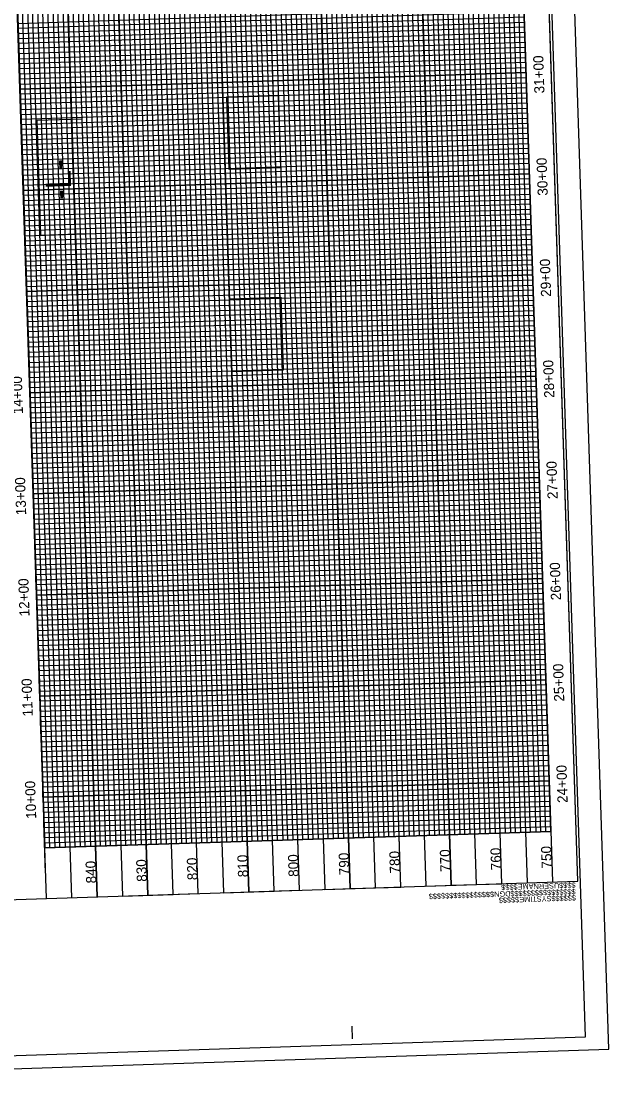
# Model space of a CAD drawing. Extents: x 1627314 to 1628469, y 762309 to 764212.
# Drawn here: x 1627889 to 1628469, y 762309 to 763361 of the extents above; entities that cross this region are included whole.
import ezdxf

# ---------------------------------------------------------------- set-up
doc = ezdxf.new("R2010")
doc.units = 0
for name, color, linetype in [('Exist Vertical Profile Horizontal Axis Label Major', 7, 'Continuous'), ('Exist Vertical Profile Vertical Axis Label', 7, 'Continuous'), ('Prop DSN Text', 7, 'Continuous'), ('Prop Grid Mask', 7, 'Continuous'), ('Sheet DOT Grid CELL', 7, 'Continuous'), ('Sheet Layout Profile Border Port 2', 7, 'Continuous'), ('Sheet Plot Border Inside CELL', 7, 'Continuous'), ('Sheet Plot Border Outside CELL', 7, 'Continuous'), ('Sheet Profile CELL', 7, 'Continuous'), ('Sheet Profile Grid Major CELL', 7, 'Continuous'), ('Sheet Profile Grid Middle CELL', 7, 'Continuous'), ('Sheet Profile Grid Minor CELL', 7, 'Continuous')]:
    doc.layers.add(name, color=color, linetype=linetype)

msp = doc.modelspace()

# ---------------------------------------------------------------- linework, layer by layer
at = {"layer": 'Prop Grid Mask'}
for points in [[(1628094.6, 763214.4), (1628092.3, 763286.3), (1628142.9, 763288), (1628145.2, 763216)], [(1627952.9, 763151.2), (1627949.2, 763264.2), (1627904.5, 763262.7), (1627908.2, 763149.7)], [(1628097.1, 763014.6), (1628094.8, 763086.6), (1628145.4, 763088.2), (1628147.8, 763016.3)]]:
    msp.add_lwpolyline(points, close=True, dxfattribs=at)
at = {"layer": 'Sheet DOT Grid CELL'}
for p, q in [((1628213.9, 762504), (1628164.8, 764003.1)), ((1628263.9, 762505.6), (1628214.8, 764004.7)), ((1628313.8, 762507.3), (1628264.8, 764006.4)), ((1628363.8, 762508.9), (1628314.8, 764008)), ((1627914, 762494.2), (1627865, 763993.3)), ((1627964, 762495.8), (1627915, 763994.9)), ((1628014, 762497.5), (1627965, 763996.6)), ((1628064, 762499.1), (1628014.9, 763998.2)), ((1628113.9, 762500.7), (1628064.9, 763999.8)), ((1628163.9, 762502.4), (1628114.9, 764001.5)), ((1627886.3, 763343.8), (1628386, 763360.1)), ((1627887.9, 763293.8), (1628387.6, 763310.1)), ((1627889.5, 763243.8), (1628389.3, 763260.2)), ((1627891.2, 763193.8), (1628390.9, 763210.2)), ((1627892.8, 763143.9), (1628392.5, 763160.2)), ((1627894.4, 763093.9), (1628394.2, 763110.2)), ((1627896.1, 763043.9), (1628395.8, 763060.3)), ((1627897.7, 762993.9), (1628397.4, 763010.3)), ((1627899.3, 762944), (1628399.1, 762960.3)), ((1627901, 762894), (1628400.7, 762910.3)), ((1627902.6, 762844), (1628402.3, 762860.4)), ((1627904.2, 762794), (1628404, 762810.4)), ((1627905.9, 762744.1), (1628405.6, 762760.4)), ((1627907.5, 762694.1), (1628407.2, 762710.4)), ((1627909.1, 762644.1), (1628408.9, 762660.5)), ((1627910.8, 762594.2), (1628410.5, 762610.5)), ((1627912.4, 762544.2), (1628412.1, 762560.5))]:
    msp.add_line(p, q, dxfattribs=at)
at = {"layer": 'Sheet Layout Profile Border Port 2'}
for points in [[(1627912.4, 762544.2), (1627866.6, 763943.4), (1628366.4, 763959.8), (1628412.1, 762560.5)], [(1627912.4, 762544.2), (1628412.1, 762560.5), (1628366.4, 763959.8), (1627866.6, 763943.4)]]:
    msp.add_lwpolyline(points, close=True, dxfattribs=at)
at = {"layer": 'Sheet Plot Border Inside CELL'}
msp.add_lwpolyline([(1628446.3, 762357.5), (1628391.9, 764023.1), (1627337.3, 763988.6), (1627391.8, 762323)], close=True, dxfattribs=at)
at = {"layer": 'Sheet Plot Border Outside CELL'}
msp.add_lwpolyline([(1628469.2, 762345.3), (1628413.6, 764044.4), (1627314.2, 764008.4), (1627369.8, 762309.3)], close=True, dxfattribs=at)
at = {"layer": 'Sheet Profile CELL'}
for p, q in [((1628364.7, 764009.7), (1628413.8, 762510.6)), ((1628438.8, 762511.4), (1628389.7, 764010.6)), ((1627914, 762494.2), (1627865, 763993.4)), ((1628438.8, 762511.4), (1628438.8, 762511.4)), ((1628438.8, 762511.4), (1628438.8, 762511.4)), ((1628438.8, 762511.4), (1628438.8, 762511.4)), ((1628438.8, 762511.4), (1628438.8, 762511.4)), ((1628438.8, 762511.4), (1628438.8, 762511.4)), ((1628438.8, 762511.4), (1628438.8, 762511.4)), ((1628438.8, 762511.4), (1628438.8, 762511.4)), ((1628216.2, 762355.5), (1628215.8, 762368))]:
    msp.add_line(p, q, dxfattribs=at)
msp.add_lwpolyline([(1627340.3, 763976.2), (1627389.3, 762477), (1628438.8, 762511.4), (1628389.7, 764010.6)], close=True, dxfattribs=at)
msp.add_lwpolyline([(1628437.5, 762548.8), (1628437.5, 762548.8)], dxfattribs=at)
at = {"layer": 'Sheet Profile Grid Major CELL'}
for p, q in [((1627891.2, 763193.8), (1627889.5, 763243.8)), ((1627894.4, 763093.9), (1627892.8, 763143.9)), ((1627897.7, 762993.9), (1627896.1, 763043.9)), ((1628413.8, 762510.6), (1628413.8, 762510.6))]:
    msp.add_line(p, q, dxfattribs=at)
for points in [[(1628164.8, 764003.2), (1628213.9, 762504), (1628263.9, 762505.6), (1628214.8, 764004.8)], [(1628264.8, 764006.5), (1628313.8, 762507.3), (1628313.8, 762507.3), (1628363.8, 762508.9), (1628314.8, 764008.1)], [(1628364.7, 764009.7), (1628413.8, 762510.6)], [(1627915, 763995), (1627964, 762495.8)], [(1627964.9, 763996.7), (1628014, 762497.5), (1628064, 762499.1), (1628014.9, 763998.3)], [(1628064.9, 763999.9), (1628113.9, 762500.7), (1628163.9, 762502.4), (1628114.9, 764001.6)], [(1627886.3, 763343.8), (1628386, 763360.1), (1628384.4, 763410.1)], [(1627912.4, 762544.2), (1628412.1, 762560.5), (1628410.5, 762610.5), (1627910.8, 762594.2), (1627909.1, 762644.1), (1628408.9, 762660.5), (1628407.2, 762710.4), (1627907.5, 762694.1), (1627905.9, 762744.1), (1628405.6, 762760.4), (1628404, 762810.4), (1627904.2, 762794), (1627902.6, 762844), (1628402.3, 762860.4), (1628400.7, 762910.3), (1627901, 762894), (1627899.3, 762944), (1628399.1, 762960.3), (1628397.4, 763010.3), (1627897.7, 762993.9), (1627896.1, 763043.9), (1628395.8, 763060.3), (1628394.2, 763110.2), (1627894.4, 763093.9), (1627892.8, 763143.9), (1628392.5, 763160.2), (1628390.9, 763210.2), (1627891.2, 763193.8), (1627889.5, 763243.8), (1628389.3, 763260.2), (1628387.6, 763310.1), (1627887.9, 763293.8)]]:
    msp.add_lwpolyline(points, dxfattribs=at)
at = {"layer": 'Sheet Profile Grid Middle CELL'}
for points in [[(1628139.9, 764002.4), (1628188.9, 762503.2), (1628238.9, 762504.8), (1628189.8, 764004)], [(1628239.8, 764005.7), (1628288.8, 762506.5), (1628338.8, 762508.1), (1628289.8, 764007.3)], [(1628339.7, 764008.9), (1628388.8, 762509.7)], [(1627939, 762495), (1627890, 763994.2)], [(1627940, 763995.9), (1627989, 762496.7), (1628039, 762498.3), (1627989.9, 763997.5)], [(1628039.9, 763999.1), (1628088.9, 762499.9), (1628138.9, 762501.6), (1628089.9, 764000.8)], [(1627913.2, 762519.2), (1627911.6, 762569.2), (1628411.3, 762585.5), (1628409.7, 762635.5), (1627910, 762619.1), (1627908.3, 762669.1), (1628408.1, 762685.5), (1628406.4, 762735.4), (1627906.7, 762719.1), (1627905.1, 762769.1), (1628404.8, 762785.4), (1628403.1, 762835.4), (1627903.4, 762819), (1627901.8, 762869), (1628401.5, 762885.4), (1628399.9, 762935.3), (1627900.1, 762919), (1627898.5, 762969), (1628398.2, 762985.3), (1628396.6, 763035.3), (1627896.9, 763018.9), (1627895.2, 763068.9), (1628395, 763085.2), (1628393.3, 763135.2), (1628393.3, 763135.2), (1627893.6, 763118.9), (1627892, 763168.8), (1628391.7, 763185.2), (1628390.1, 763235.2), (1627890.3, 763218.8), (1627888.7, 763268.8), (1628388.4, 763285.1), (1628386.8, 763335.1), (1627887.1, 763318.8)]]:
    msp.add_lwpolyline(points, dxfattribs=at)
at = {"layer": 'Sheet Profile Grid Minor CELL'}
for p, q in [((1628061.5, 763949.8), (1628107.2, 762550.5)), ((1628117.3, 762550.9), (1628071.5, 763950.1)), ((1628076.5, 763950.3), (1628122.3, 762551)), ((1628127.3, 762551.2), (1628081.5, 763950.5)), ((1628086.5, 763950.6), (1628132.3, 762551.4)), ((1628142.3, 762551.7), (1628096.5, 763950.9)), ((1628101.5, 763951.1), (1628147.3, 762551.9)), ((1628152.3, 762552), (1628106.5, 763951.3)), ((1628111.5, 763951.4), (1628157.3, 762552.2)), ((1628167.3, 762552.5), (1628121.5, 763951.8)), ((1628126.5, 763951.9), (1628172.3, 762552.7)), ((1628177.3, 762552.8), (1628131.5, 763952.1)), ((1628136.5, 763952.3), (1628182.3, 762553)), ((1628192.3, 762553.3), (1628146.5, 763952.6)), ((1628151.5, 763952.7), (1628197.3, 762553.5)), ((1628202.3, 762553.7), (1628156.5, 763952.9)), ((1628161.5, 763953.1), (1628207.2, 762553.8)), ((1628217.2, 762554.1), (1628171.5, 763953.4)), ((1628176.5, 763953.6), (1628222.2, 762554.3)), ((1628227.2, 762554.5), (1628181.5, 763953.7)), ((1628186.5, 763953.9), (1628232.2, 762554.6)), ((1628242.2, 762555), (1628196.5, 763954.2)), ((1628201.5, 763954.4), (1628247.2, 762555.1)), ((1628252.2, 762555.3), (1628206.5, 763954.5)), ((1628211.5, 763954.7), (1628257.2, 762555.5)), ((1628267.2, 762555.8), (1628221.4, 763955)), ((1628226.4, 763955.2), (1628272.2, 762555.9)), ((1628277.2, 762556.1), (1628231.4, 763955.4)), ((1628236.4, 763955.5), (1628282.2, 762556.3)), ((1628292.2, 762556.6), (1628246.4, 763955.9)), ((1628251.4, 763956), (1628297.2, 762556.8)), ((1628302.2, 762556.9), (1628256.4, 763956.2)), ((1628261.4, 763956.3), (1628307.2, 762557.1)), ((1628317.2, 762557.4), (1628271.4, 763956.7)), ((1628276.4, 763956.8), (1628322.2, 762557.6)), ((1628327.2, 762557.7), (1628281.4, 763957)), ((1628286.4, 763957.2), (1628332.2, 762557.9)), ((1628342.2, 762558.2), (1628296.4, 763957.5)), ((1628301.4, 763957.7), (1628347.2, 762558.4)), ((1628352.2, 762558.6), (1628306.4, 763957.8)), ((1628311.4, 763958), (1628357.2, 762558.7)), ((1628367.2, 762559.1), (1628321.4, 763958.3)), ((1628326.4, 763958.5), (1628372.2, 762559.2)), ((1628377.2, 762559.4), (1628331.4, 763958.6)), ((1628336.4, 763958.8), (1628382.2, 762559.5)), ((1628392.1, 762559.9), (1628346.4, 763959.1)), ((1628351.4, 763959.3), (1628397.1, 762560)), ((1628402.1, 762560.2), (1628356.4, 763959.4)), ((1628407.1, 762560.4), (1628361.4, 763959.6)), ((1627917.4, 762544.3), (1627871.6, 763943.6)), ((1627876.6, 763943.8), (1627922.4, 762544.5)), ((1627927.4, 762544.7), (1627881.6, 763943.9)), ((1627886.6, 763944.1), (1627932.4, 762544.8)), ((1627942.4, 762545.2), (1627896.6, 763944.4)), ((1627901.6, 763944.6), (1627947.4, 762545.3)), ((1627952.4, 762545.5), (1627906.6, 763944.7)), ((1627911.6, 763944.9), (1627957.4, 762545.6)), ((1627967.4, 762546), (1627921.6, 763945.2)), ((1627926.6, 763945.4), (1627972.4, 762546.1)), ((1627977.4, 762546.3), (1627931.6, 763945.6)), ((1627936.6, 763945.7), (1627982.4, 762546.5)), ((1627992.4, 762546.8), (1627946.6, 763946)), ((1627951.6, 763946.2), (1627997.4, 762547)), ((1628002.4, 762547.1), (1627956.6, 763946.4)), ((1627961.6, 763946.5), (1628007.4, 762547.3)), ((1628017.4, 762547.6), (1627971.6, 763946.9)), ((1627976.6, 763947), (1628022.3, 762547.8)), ((1628027.3, 762547.9), (1627981.6, 763947.2)), ((1627986.6, 763947.4), (1628032.3, 762548.1)), ((1628042.3, 762548.4), (1627996.6, 763947.7)), ((1628001.6, 763947.8), (1628047.3, 762548.6)), ((1628052.3, 762548.8), (1628006.6, 763948)), ((1628011.6, 763948.2), (1628057.3, 762548.9)), ((1628067.3, 762549.2), (1628021.6, 763948.5)), ((1628026.6, 763948.7), (1628072.3, 762549.4)), ((1628077.3, 762549.6), (1628031.5, 763948.8)), ((1628036.5, 763949), (1628082.3, 762549.7)), ((1628092.3, 762550.1), (1628046.5, 763949.3)), ((1628051.5, 763949.5), (1628097.3, 762550.2)), ((1628102.3, 762550.4), (1628056.5, 763949.6))]:
    msp.add_line(p, q, dxfattribs=at)
for points in [[(1628385.7, 763370.1), (1627885.9, 763353.7), (1627885.8, 763358.7), (1628385.5, 763375.1)], [(1627886.1, 763348.7), (1628385.8, 763365.1)], [(1627886.6, 763333.8), (1628386.3, 763350.1), (1628386.1, 763355.1), (1627886.4, 763338.8)], [(1627886.9, 763323.8), (1628386.6, 763340.1), (1628386.5, 763345.1), (1627886.7, 763328.8)], [(1627887.4, 763308.8), (1628387.1, 763325.1), (1628387, 763330.1), (1627887.2, 763313.8)], [(1627887.7, 763298.8), (1628387.5, 763315.1), (1628387.3, 763320.1), (1627887.6, 763303.8)], [(1627888.2, 763283.8), (1628387.9, 763300.1), (1628387.8, 763305.1), (1627888.1, 763288.8)], [(1627888.5, 763273.8), (1628388.3, 763290.1), (1628388.1, 763295.1), (1627888.4, 763278.8)], [(1627889, 763258.8), (1628388.8, 763275.1), (1628388.6, 763280.1), (1627888.9, 763263.8)], [(1627895.1, 763073.9), (1628394.8, 763090.2), (1628394.6, 763095.2), (1627894.9, 763078.9), (1627894.8, 763083.9), (1628394.5, 763100.2), (1628394.3, 763105.2), (1627894.6, 763088.9), (1627894.3, 763098.9), (1628394, 763115.2), (1628393.8, 763120.2), (1627894.1, 763103.9), (1627893.9, 763108.9), (1628393.7, 763125.2), (1628393.5, 763130.2), (1627893.8, 763113.9), (1627893.4, 763123.9), (1628393.2, 763140.2), (1628393, 763145.2), (1627893.3, 763128.9), (1627893.1, 763133.9), (1628392.9, 763150.2), (1628392.7, 763155.2), (1627893, 763138.9), (1627892.6, 763148.9), (1628392.4, 763165.2), (1628392.2, 763170.2), (1627892.5, 763153.9), (1627892.3, 763158.8), (1628392, 763175.2), (1628391.9, 763180.2), (1627892.1, 763163.8), (1627891.8, 763173.8), (1628391.5, 763190.2), (1628391.4, 763195.2), (1627891.6, 763178.8), (1627891.5, 763183.8), (1628391.2, 763200.2), (1628391.1, 763205.2), (1627891.3, 763188.8), (1627891, 763198.8), (1628390.7, 763215.2), (1628390.7, 763215.2), (1628390.6, 763220.2), (1627890.8, 763203.8), (1627890.7, 763208.8), (1628390.4, 763225.2), (1628390.2, 763230.2), (1627890.5, 763213.8), (1627890.2, 763223.8), (1628389.9, 763240.2), (1628389.7, 763245.2), (1627890, 763228.8), (1627889.8, 763233.8), (1628389.6, 763250.2), (1628389.4, 763255.2), (1627889.7, 763238.8), (1627889.4, 763248.8), (1628389.1, 763265.1), (1628388.9, 763270.1), (1627889.2, 763253.8)], [(1628405.1, 762775.4), (1628404.9, 762780.4), (1627905.2, 762764.1), (1627904.9, 762774.1), (1628404.6, 762790.4), (1628404.5, 762795.4), (1627904.7, 762779.1), (1627904.6, 762784), (1628404.3, 762800.4), (1628404.1, 762805.4), (1627904.4, 762789), (1627904.1, 762799), (1628403.8, 762815.4), (1628403.6, 762820.4), (1627903.9, 762804), (1627903.7, 762809), (1628403.5, 762825.4), (1628403.3, 762830.4), (1627903.6, 762814), (1627903.3, 762824), (1628403, 762840.4), (1628402.8, 762845.4), (1627903.1, 762829), (1627902.9, 762834), (1628402.7, 762850.4), (1628402.5, 762855.4), (1627902.8, 762839), (1627902.4, 762849), (1628402.2, 762865.4), (1628402, 762870.4), (1627902.3, 762854), (1627902.1, 762859), (1628401.8, 762875.4), (1628401.7, 762880.4), (1627901.9, 762864), (1627901.6, 762874), (1628401.4, 762890.3), (1628401.2, 762895.3), (1627901.5, 762879), (1627901.3, 762884), (1628401, 762900.3), (1628400.9, 762905.3), (1627901.1, 762889), (1627900.8, 762899), (1628400.5, 762915.3), (1628400.4, 762920.3), (1627900.6, 762904), (1627900.5, 762909), (1628400.2, 762925.3), (1628400, 762930.3), (1627900.3, 762914), (1627900, 762924), (1628399.7, 762940.3), (1628399.6, 762945.3), (1627899.8, 762929), (1627899.7, 762934), (1628399.4, 762950.3), (1628399.2, 762955.3), (1627899.5, 762939), (1627899.2, 762949), (1628398.9, 762965.3), (1628398.7, 762970.3), (1627899, 762954), (1627898.8, 762959), (1628398.6, 762975.3), (1628398.4, 762980.3), (1627898.7, 762964), (1627898.3, 762973.9), (1628398.1, 762990.3), (1628397.9, 762995.3), (1627898.2, 762978.9), (1627898, 762983.9), (1628397.8, 763000.3), (1628397.6, 763005.3), (1627897.9, 762988.9), (1627897.5, 762998.9), (1628397.3, 763015.3), (1628397.1, 763020.3), (1627897.4, 763003.9), (1627897.2, 763008.9), (1628396.9, 763025.3), (1628396.8, 763030.3), (1627897, 763013.9), (1627896.7, 763023.9), (1628396.4, 763040.3), (1628396.3, 763045.3), (1627896.6, 763028.9), (1627896.4, 763033.9), (1628396.1, 763050.3), (1628396, 763055.3), (1627896.2, 763038.9), (1627895.9, 763048.9), (1628395.6, 763065.3), (1628395.5, 763070.3), (1627895.7, 763053.9), (1627895.6, 763058.9), (1628395.3, 763075.2), (1628395.1, 763080.2), (1627895.4, 763063.9), (1627895.1, 763073.9)], [(1627912.4, 762544.2), (1627912.2, 762549.2), (1628412, 762565.5), (1628411.8, 762570.5), (1627912.1, 762554.2), (1627911.9, 762559.2), (1628411.6, 762575.5), (1628411.5, 762580.5), (1627911.8, 762564.2), (1627911.4, 762574.2), (1628411.2, 762590.5), (1628411, 762595.5), (1627911.3, 762579.2), (1627911.1, 762584.2), (1628410.8, 762600.5), (1628410.7, 762605.5), (1628410.3, 762615.5), (1628410.2, 762620.5), (1627910.4, 762604.1), (1627910.3, 762609.1), (1628410, 762625.5), (1628409.9, 762630.5), (1627910.1, 762614.1), (1627909.8, 762624.1), (1628409.5, 762640.5), (1628409.4, 762645.5), (1627909.6, 762629.1), (1627909.5, 762634.1), (1628409.2, 762650.5), (1628409, 762655.5), (1627909.3, 762639.1), (1627909, 762649.1), (1628408.7, 762665.5), (1628408.5, 762670.5), (1627908.8, 762654.1), (1627908.6, 762659.1), (1628408.4, 762675.5), (1628408.2, 762680.5), (1627908.5, 762664.1), (1627908.2, 762674.1), (1628407.9, 762690.5), (1628407.7, 762695.5), (1627908, 762679.1), (1627907.8, 762684.1), (1628407.6, 762700.4), (1628407.4, 762705.4), (1627907.7, 762689.1), (1627907.3, 762699.1), (1628407.1, 762715.4), (1628406.9, 762720.4), (1627907.2, 762704.1), (1627907, 762709.1), (1628406.7, 762725.4), (1628406.6, 762730.4), (1627906.8, 762714.1), (1627906.5, 762724.1), (1628406.3, 762740.4), (1628406.1, 762745.4), (1627906.4, 762729.1), (1627906.2, 762734.1), (1628405.9, 762750.4), (1628405.8, 762755.4), (1627906, 762739.1), (1627905.7, 762749.1), (1628405.4, 762765.4), (1628405.3, 762770.4), (1627905.5, 762754.1), (1627905.4, 762759.1), (1628405.1, 762775.4)], [(1628410.7, 762605.5), (1627910.9, 762589.2), (1627910.6, 762599.1), (1628410.3, 762615.5)]]:
    msp.add_lwpolyline(points, dxfattribs=at)

# ---------------------------------------------------------------- texts
at = {"layer": 'Exist Vertical Profile Horizontal Axis Label Major'}
for s, p in [('31+00', (1628405.8, 763289.7)), ('30+00', (1628409.1, 763188.7)), ('29+00', (1628412.4, 763088.8)), ('28+00', (1628415.6, 762988.9)), ('14+00', (1627890.9, 762972.9)), ('27+00', (1628418.9, 762889)), ('13+00', (1627894.1, 762873)), ('26+00', (1628422.2, 762789)), ('12+00', (1627897.4, 762773.1)), ('25+00', (1628425.4, 762688.9)), ('11+00', (1627900.6, 762674.3)), ('24+00', (1628428.7, 762588.8)), ('10+00', (1627904, 762573.1))]:
    msp.add_text(s, height=10, rotation=91.8735, dxfattribs=at).set_placement(p)
at = {"layer": 'Exist Vertical Profile Vertical Axis Label'}
for s, p in [('780', (1628263.2, 762519.1)), ('770', (1628313.1, 762520.7)), ('760', (1628363.1, 762522.3)), ('750', (1628413.1, 762524)), ('840', (1627963.3, 762509.3)), ('830', (1628013.3, 762510.9)), ('820', (1628063.3, 762512.5)), ('810', (1628113.2, 762515.4)), ('800', (1628163.2, 762515.8)), ('790', (1628213.2, 762517.4))]:
    msp.add_text(s, height=10, rotation=91.8735, dxfattribs=at).set_placement(p)
at = {"layer": 'Prop DSN Text'}
msp.add_text('-L-', height=25, rotation=91.8735, dxfattribs=at).set_placement((1627938.8, 763184.3))
at = {"layer": 'Sheet Profile CELL'}
for s, p in [('$$$$USERNAME$$$$', (1628436.4, 762510.2)), ('$$$$$$$$$$$$$$$$DGN$$$$$$$$$$$$$$$$', (1628436.6, 762503.7)), ('$$$$$$SYSTIME$$$$$', (1628436.8, 762497.6))]:
    msp.add_text(s, height=5.25, rotation=181.8735, dxfattribs=at).set_placement(p)

doc.saveas('drawing.dxf')
